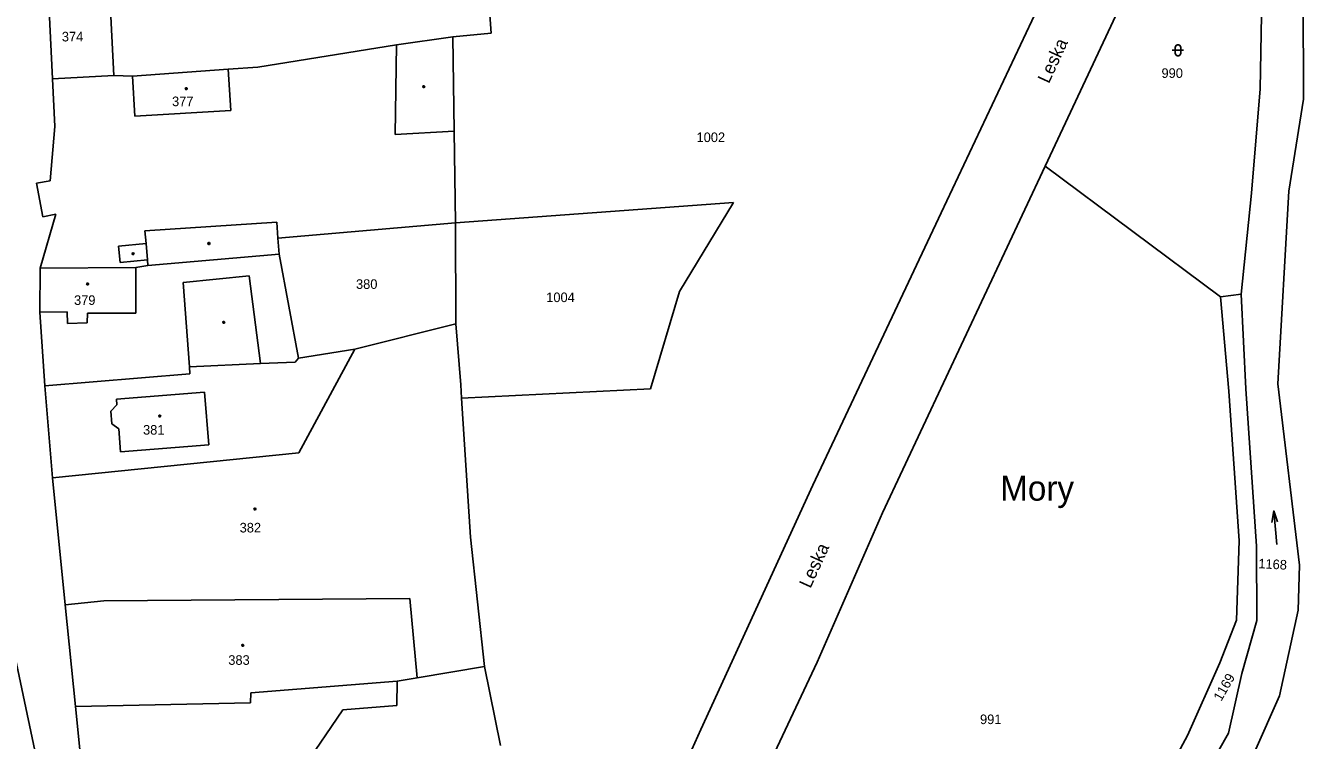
# Model space of a CAD drawing. Extents: x -812394 to -807601, y -1013097 to -1009266.
# Drawn here: x -810997.7 to -810771.4, y -1011538.5 to -1011411.9 of the extents above; entities that cross this region are included whole.
import ezdxf

# ---------------------------------------------------------------- set-up
doc = ezdxf.new("R2010")
doc.units = 0
for name, color, linetype in [('Default', 7, 'Continuous'), ('KN_HRANICE', 7, 'Continuous'), ('KN_KULTURY', 7, 'Continuous'), ('KN_PARCELY', 7, 'Continuous'), ('KN_SLUCKY', 7, 'Continuous')]:
    doc.layers.add(name, color=color, linetype=linetype)

# ---------------------------------------------------------------- blocks, each defined once
blk = doc.blocks.new('316')
at = {"layer": 'Default'}
for points in [[(-1, 1), (0.27, 1), (1, 1)], [(-0.5, 1.5), (-0.4, 1.79), (-0.15, 1.97), (0.16, 1.97), (0.41, 1.79), (0.51, 1.5), (0.51, 0.5), (0.41, 0.21), (0.16, 0.03), (-0.15, 0.03), (-0.4, 0.21), (-0.5, 0.5), (-0.5, 1.5)]]:
    blk.add_lwpolyline(points, dxfattribs=at)
blk = doc.blocks.new('NAHRADNI_SYMBOL')
at = {"layer": 'Default'}
blk.add_lwpolyline([(0.09, 0.15), (0.18, 0), (0.09, -0.15), (-0.09, -0.15), (-0.18, 0), (-0.09, 0.15), (0.09, 0.15)], dxfattribs=at)
blk = doc.blocks.new('802')
at = {"layer": 'Default'}
blk.add_line((-3, 0), (3, 0), dxfattribs=at)
blk.add_lwpolyline([(1, 0.5), (3, 0), (1, -0.5)], dxfattribs=at)
blk = doc.blocks.new('402')
at = {"layer": 'Default'}
blk.add_lwpolyline([(0.09, 0.15), (0.18, 0), (0.09, -0.15), (-0.09, -0.15), (-0.18, 0), (-0.09, 0.15), (0.09, 0.15)], dxfattribs=at)

msp = doc.modelspace()

# ---------------------------------------------------------------- linework, layer by layer
at = {"layer": 'KN_HRANICE'}
for p, q in [((-810835.54, -1011445.05), (-810807.37, -1011385.45)), ((-810915.25, -1011413.2), (-810916.55, -1011393.72)), ((-810771.46, -1011394.94), (-810771.36, -1011424.92)), ((-810992.93, -1011421.31), (-810993.69, -1011405.27)), ((-810921.99, -1011413.85), (-810931.99, -1011415.27)), ((-810921.99, -1011413.85), (-810915.25, -1011413.2)), ((-810921.99, -1011413.85), (-810921.79, -1011430.55)), ((-810956.57, -1011419.22), (-810931.99, -1011415.27)), ((-810982.08, -1011420.69), (-810992.93, -1011421.31)), ((-810992.53, -1011429.75), (-810992.93, -1011421.31)), ((-810982.08, -1011420.69), (-810978.74, -1011420.81)), ((-810978.74, -1011420.81), (-810961.79, -1011419.59)), ((-810961.79, -1011419.59), (-810956.57, -1011419.22)), ((-810771.36, -1011424.92), (-810773.93, -1011441.2)), ((-810993.32, -1011439.39), (-810992.53, -1011429.75)), ((-810921.79, -1011430.55), (-810921.54, -1011446.8)), ((-810786.05, -1011459.9), (-810817.11, -1011436.78)), ((-810995.78, -1011439.78), (-810993.32, -1011439.39)), ((-810994.65, -1011445.73), (-810995.78, -1011439.78)), ((-810773.93, -1011441.2), (-810775.87, -1011475.3)), ((-810872.3, -1011443.19), (-810921.54, -1011446.8)), ((-810881.86, -1011458.96), (-810872.3, -1011443.19)), ((-810995.12, -1011454.86), (-810992.33, -1011445.29)), ((-810992.33, -1011445.29), (-810994.65, -1011445.73)), ((-810858.26, -1011493.31), (-810835.54, -1011445.05)), ((-810931.8, -1011447.68), (-810952.99, -1011449.5)), ((-810921.54, -1011446.8), (-810931.8, -1011447.68)), ((-810921.46, -1011464.71), (-810921.54, -1011446.8)), ((-810952.99, -1011449.5), (-810952.79, -1011452.34)), ((-810952.79, -1011452.34), (-810976.02, -1011454.34)), ((-810952.79, -1011452.34), (-810949.37, -1011470.8)), ((-810995.17, -1011462.65), (-810995.12, -1011454.86)), ((-810995.12, -1011454.86), (-810978.15, -1011454.73)), ((-810978.15, -1011454.73), (-810976.02, -1011454.34)), ((-810887.03, -1011476.21), (-810881.86, -1011458.96)), ((-810786.05, -1011459.9), (-810782.41, -1011459.43)), ((-810784.57, -1011476.64), (-810786.05, -1011459.9)), ((-810994.25, -1011475.67), (-810995.17, -1011462.65)), ((-810939.39, -1011469.21), (-810921.46, -1011464.71)), ((-810920.62, -1011475.48), (-810921.46, -1011464.71)), ((-810949.91, -1011471.49), (-810949.37, -1011470.8)), ((-810949.37, -1011470.8), (-810939.39, -1011469.21)), ((-810949.29, -1011487.58), (-810939.39, -1011469.21)), ((-810968.68, -1011472.29), (-810956.08, -1011471.75)), ((-810968.61, -1011473.55), (-810968.68, -1011472.29)), ((-810956.08, -1011471.75), (-810949.91, -1011471.49)), ((-810994.25, -1011475.67), (-810968.61, -1011473.55)), ((-810920.46, -1011477.89), (-810920.62, -1011475.48)), ((-810992.93, -1011491.98), (-810994.25, -1011475.67)), ((-810920.46, -1011477.89), (-810887.03, -1011476.21)), ((-810918.87, -1011502.5), (-810920.46, -1011477.89)), ((-810782.75, -1011503.15), (-810784.57, -1011476.64)), ((-810992.93, -1011491.98), (-810949.29, -1011487.58)), ((-810990.65, -1011514.5), (-810992.93, -1011491.98)), ((-810878.11, -1011536.55), (-810858.26, -1011493.31)), ((-810988.29, -1011576.92), (-811004.66, -1011499.57)), ((-810916.42, -1011525.41), (-810918.87, -1011502.5)), ((-810783.24, -1011517.2), (-810782.75, -1011503.15)), ((-810983.8, -1011513.77), (-810990.65, -1011514.5)), ((-810929.63, -1011513.38), (-810983.8, -1011513.77)), ((-810928.34, -1011527.4), (-810929.63, -1011513.38)), ((-810988.82, -1011532.52), (-810990.65, -1011514.5)), ((-810786.16, -1011524.78), (-810783.24, -1011517.2)), ((-810928.34, -1011527.4), (-810916.42, -1011525.41)), ((-810913.6, -1011539.41), (-810916.42, -1011525.41)), ((-810791.91, -1011537.6), (-810786.16, -1011524.78)), ((-810931.87, -1011527.99), (-810928.34, -1011527.4)), ((-810782.3, -1011526.63), (-810784.63, -1011537.23)), ((-810931.87, -1011527.99), (-810957.81, -1011530.07)), ((-810931.91, -1011532.3), (-810931.87, -1011527.99)), ((-810957.84, -1011531.83), (-810988.82, -1011532.52)), ((-810957.81, -1011530.07), (-810957.84, -1011531.83)), ((-810987.2, -1011548.48), (-810988.82, -1011532.52)), ((-810948.4, -1011543.24), (-810941.47, -1011533.07)), ((-810941.47, -1011533.07), (-810931.91, -1011532.3)), ((-810881.34, -1011543.7), (-810878.11, -1011536.55)), ((-810800.53, -1011553.7), (-810791.91, -1011537.6)), ((-810784.63, -1011537.23), (-810795.57, -1011556.36))]:
    msp.add_line(p, q, dxfattribs=at)
for points in [[(-810817.11, -1011436.78), (-810799.71, -1011399.57), (-810781.64, -1011360.53), (-810777.84, -1011351.43)], [(-810777.84, -1011351.43), (-810779.49, -1011369.6), (-810778.58, -1011396.9), (-810779, -1011423.07), (-810780.56, -1011441.53), (-810782.41, -1011459.43)], [(-810887.79, -1011588.2), (-810877.76, -1011568.21), (-810866.95, -1011544.7), (-810857.48, -1011524.61), (-810845.94, -1011498.21), (-810817.11, -1011436.78)], [(-810782.41, -1011459.43), (-810781.54, -1011476.23), (-810779.65, -1011504.07), (-810779.6, -1011517.24), (-810782.3, -1011526.63)], [(-810786.65, -1011550.55), (-810780.03, -1011540.57), (-810775.59, -1011530.62), (-810772.3, -1011515.42), (-810772.06, -1011507.46), (-810775.87, -1011475.3)]]:
    msp.add_lwpolyline(points, dxfattribs=at)
at = {"layer": 'KN_SLUCKY'}
for p, q in [((-810982.89, -1011404.38), (-810982.08, -1011420.69)), ((-810932.22, -1011431.17), (-810931.99, -1011415.27)), ((-810978.33, -1011427.93), (-810978.74, -1011420.81)), ((-810961.36, -1011426.93), (-810961.79, -1011419.59)), ((-810978.33, -1011427.93), (-810961.36, -1011426.93)), ((-810921.79, -1011430.55), (-810932.22, -1011431.17)), ((-810953.18, -1011446.7), (-810976.54, -1011448.25)), ((-810976.35, -1011450.49), (-810976.54, -1011448.25)), ((-810953.18, -1011446.7), (-810952.99, -1011449.5)), ((-810981.24, -1011450.96), (-810976.35, -1011450.49)), ((-810976.11, -1011453.34), (-810976.35, -1011450.49)), ((-810980.96, -1011453.81), (-810981.24, -1011450.96)), ((-810976.11, -1011453.34), (-810980.96, -1011453.81)), ((-810978.15, -1011454.73), (-810978.15, -1011462.8)), ((-810976.02, -1011454.34), (-810976.11, -1011453.34)), ((-810969.76, -1011457.38), (-810958.06, -1011456.19)), ((-810968.68, -1011472.29), (-810969.76, -1011457.38)), ((-810958.06, -1011456.19), (-810956.08, -1011471.75)), ((-810990.32, -1011462.59), (-810995.17, -1011462.65)), ((-810990.26, -1011464.62), (-810990.32, -1011462.59)), ((-810986.71, -1011462.8), (-810986.76, -1011464.51)), ((-810978.15, -1011462.8), (-810986.71, -1011462.8)), ((-810986.76, -1011464.51), (-810990.26, -1011464.62)), ((-810965.99, -1011476.83), (-810981.58, -1011478.05)), ((-810965.25, -1011486.14), (-810965.99, -1011476.83)), ((-810981.51, -1011479.03), (-810982.58, -1011480.15)), ((-810982.58, -1011480.15), (-810982.4, -1011482.42)), ((-810981.58, -1011478.05), (-810981.51, -1011479.03)), ((-810982.4, -1011482.42), (-810981.17, -1011483.32)), ((-810981.17, -1011483.32), (-810980.85, -1011487.37)), ((-810980.85, -1011487.37), (-810965.25, -1011486.14))]:
    msp.add_line(p, q, dxfattribs=at)

# ---------------------------------------------------------------- block references
at = {"layer": 'KN_KULTURY'}
for name, p in [('316', (-810793.59, -1011417.24)), ('402', (-810969.23, -1011423.06)), ('402', (-810927.16, -1011422.66)), ('402', (-810965.21, -1011450.47)), ('402', (-810978.65, -1011452.29)), ('402', (-810986.71, -1011457.63)), ('402', (-810962.59, -1011464.41)), ('402', (-810973.92, -1011481.04)), ('NAHRADNI_SYMBOL', (-810957.06, -1011497.52)), ('402', (-810959.21, -1011521.65))]:
    msp.add_blockref(name, p, dxfattribs=at)
at = {"layer": 'KN_KULTURY', "rotation": 95.34017700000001}
msp.add_blockref('802', (-810776.35, -1011500.82), dxfattribs=at)

# ---------------------------------------------------------------- texts
at = {"layer": 'KN_PARCELY'}
for s, p in [('374', (-810991.26, -1011414.67)), ('990', (-810796.5, -1011421.13)), ('377', (-810971.74, -1011426.14)), ('1002', (-810878.85, -1011432.5)), ('380', (-810939.16, -1011458.51)), ('379', (-810989.1, -1011461.35)), ('1004', (-810905.47, -1011460.85)), ('381', (-810976.88, -1011484.33)), ('382', (-810959.77, -1011501.66)), ('383', (-810961.78, -1011525.11)), ('991', (-810828.64, -1011535.61))]:
    msp.add_text(s, height=1.7, dxfattribs=at).set_placement(p)
for s, height, rotation, p in [('Leska', 2.3, 65.317, (-810816.45, -1011422.26)), ('Mory', 4.4, 359.817, (-810825.08, -1011496)), ('Leska', 2.3, 65.546, (-810858.68, -1011511.69)), ('1168', 1.7, 356.953, (-810779.38, -1011507.99)), ('1169', 1.7, 60.332, (-810785.92, -1011531.67))]:
    msp.add_text(s, height=height, rotation=rotation, dxfattribs=at).set_placement(p)

doc.saveas('drawing.dxf')
